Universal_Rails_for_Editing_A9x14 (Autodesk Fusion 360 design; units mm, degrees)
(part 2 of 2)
sketch "Sketch53" plane through (0, 97.7, 0) normal (0, -1, 0) x axis (1, 0, 0)
  line L1 (241.5, 1.5) -> (241.5, 15)
  line L2 (253.5, 1.5) -> (241.5, 1.5)
  line L3 (253.5, 15) -> (253.5, 1.5)
  line L4 (241.5, 15) -> (253.5, 15)
  circle C1 centre (245.5, 9) radius 1
  circle C2 centre (247.5, 9) radius 1
  dimension "d563" diameter C2 = 2
extrude "Extrude160" cut sketch "Sketch53" profile of C2 against normal blind 4
delete_face "DeleteFace57"
sketch "Sketch54" plane through (0, 97.7, 0) normal (0, -1, 0) x axis (1, 0, 0)
  line L1 (144.5, 13.2322) -> (144.5, 1)
  line L2 (132.5, 13.2322) -> (144.5, 13.2322)
  line L3 (132.5, 1) -> (132.5, 13.2322)
  line L4 (144.5, 1) -> (132.5, 1)
  circle C1 centre (138.5, 9) radius 1
  circle C2 centre (139.5, 9) radius 1
  point P2 (138.5, 9)
  coincident P2 C2
  dimension "d566" diameter C2 = 2
extrude "Extrude161" new body sketch "Sketch54" profile of C1 C2 along normal blind 1.9
delete_face "DeleteFace58"
extrude "Extrude162" cut of existing geometry blind -14
extrude "Extrude163" cut of existing geometry blind -1
extrude "Extrude164" add of existing geometry blind 1
fillet "Fillet54" radius 3
fillet "Fillet55" radius 3
chamfer "Chamfer16" distance 0.75
chamfer "Chamfer17" distance 0.75
chamfer "Chamfer18" distance 0.75
delete_face "DeleteFace59"
delete_face "DeleteFace60"
sketch "Sketch55" plane through (0, 99.2, 0) normal (0, 1, 0) x axis (-1, 0, 0)
  line L1 (-279, 4) -> (-279, 12.5)
  line L2 (-5, -1) -> (-274, -1)
  line L3 (0, 12.5) -> (0, 4)
  line L4 (-25, 15) -> (-2.5, 15)
  line L5 (-26.7678, 13.2322) -> (-25, 15)
  line L6 (-226.7678, 13.2322) -> (-26.7678, 13.2322)
  line L7 (-228.5355, 15) -> (-226.7678, 13.2322)
  line L8 (-276.5, 15) -> (-228.5355, 15)
  circle C1 centre (-139.5, 9) radius 1
  circle C2 centre (-12, 9) radius 1.75
  arc A1 centre (-276.5, 12.5) radius 2.5 clockwise from (-279, 12.5) to (-276.5, 15)
  arc A2 centre (-274, 4) radius 5 clockwise from (-274, -1) to (-279, 4)
  arc A3 centre (-5, 4) radius 5 clockwise from (0, 4) to (-5, -1)
  arc A4 centre (-2.5, 12.5) radius 2.5 clockwise from (-2.5, 15) to (0, 12.5)
  circle C3 centre (-140.5, 9) radius 1
  circle C4 centre (-248, 9) radius 1
  point P20 (-140.5, 9)
  coincident C1 P20
  dimension "d582" diameter C3 = 2
  dimension "d583" diameter C4 = 2
extrude "Extrude165" new body sketch "Sketch55" profile of C4 against normal blind 1.5
extrude "Extrude166" new body sketch "Sketch55" profile of C4 along normal blind 5.2
extrude "Extrude167" cut of existing geometry blind -29.5
extrude "Extrude168" add sketch "Sketch55" profile of C1 C3 along normal blind 2
extrude "Extrude169" new body sketch "Sketch55" profile of C1 C3 against normal blind 1.5
extrude "Extrude170" cut of existing geometry blind -19
delete_face "DeleteFace61"
extrude "Extrude171" cut of existing geometry blind -1
fillet "Fillet56" radius 3
combine "Combine10"
delete_face "DeleteFace62"
extrude "Extrude172" cut of existing geometry blind -0.5
fillet "Fillet57" radius 3
extrude "Extrude173" cut of existing geometry blind -2.1
extrude "Extrude174" add of existing geometry blind 2.4
delete_face "DeleteFace63"
extrude "Extrude175" add of existing geometry blind 2.4
delete_face "DeleteFace64"
extrude "Extrude176" add of existing geometry blind 2.4
delete_face "DeleteFace65"
delete_face "DeleteFace66"
delete_face "DeleteFace67"
delete_face "DeleteFace68"
delete_face "DeleteFace69"
delete_face "DeleteFace70"
delete_face "DeleteFace71"
delete_face "DeleteFace72"
delete_face "DeleteFace73"
delete_face "DeleteFace74"
delete_face "DeleteFace75"
delete_face "DeleteFace76"
delete_face "DeleteFace77"
delete_face "DeleteFace78"
delete_face "DeleteFace79"
delete_face "DeleteFace80"
delete_face "DeleteFace81"
delete_face "DeleteFace82"
extrude "Extrude177" add of existing geometry blind 6.35
delete_face "DeleteFace83"
delete_face "DeleteFace84"
delete_face "DeleteFace85"
delete_face "DeleteFace86"
delete_face "DeleteFace87"
delete_face "DeleteFace88"
delete_face "DeleteFace89"
delete_face "DeleteFace90"
delete_face "DeleteFace91"
delete_face "DeleteFace92"
delete_face "DeleteFace93"
delete_face "DeleteFace94"
delete_face "DeleteFace95"
delete_face "DeleteFace96"
delete_face "DeleteFace97"
delete_face "DeleteFace98"
delete_face "DeleteFace99"
delete_face "DeleteFace100"
delete_face "DeleteFace101"
delete_face "DeleteFace102"
delete_face "DeleteFace103"
extrude "Extrude178" add of existing geometry blind 5.55
delete_face "DeleteFace104"
delete_face "DeleteFace105"
delete_face "DeleteFace106"
delete_face "DeleteFace107"
sketch "Sketch56" plane through (0, 3.05, 0) normal (0, 1, 0) x axis (-1, 0, 0)
  line L1 (-26.4528, 4.7) -> (-18, 4.7)
  line L2 (-26.4523, 6.2374) -> (-26.4528, 4.7)
  line L3 (-26.4524, 6.5) -> (-26.4523, 6.2374)
  line L4 (-18, 6.5) -> (-26.4524, 6.5)
  line L5 (-18, 4.7) -> (-18, 6.5)
  line L6 (-18, 10.3) -> (-26.4528, 10.3)
  line L7 (-18, 8.5) -> (-18, 10.3)
  line L8 (-26.4524, 8.5) -> (-18, 8.5)
  line L9 (-26.4523, 8.7626) -> (-26.4524, 8.5)
  line L10 (-26.4528, 10.3) -> (-26.4523, 8.7626)
  line L11 (-0.5307, 10.3) -> (-6, 10.3)
  line L12 (-0.5307, 8.5) -> (-0.5307, 10.3)
  line L13 (-6, 8.5) -> (-0.5307, 8.5)
  line L14 (-6, 10.3) -> (-6, 8.5)
  line L15 (-118.9528, 4.7) -> (-93.0307, 4.7)
  line L16 (-118.9523, 6.2374) -> (-118.9528, 4.7)
  line L17 (-118.9524, 6.5) -> (-118.9523, 6.2374)
  line L18 (-93.0307, 6.5) -> (-118.9524, 6.5)
  line L19 (-93.0307, 4.7) -> (-93.0307, 6.5)
  line L20 (-158.6084, 10) -> (-157.0472, 10)
  line L21 (-158.6088, 8.7626) -> (-158.6084, 10)
  line L22 (-158.6088, 8.5) -> (-158.6088, 8.7626)
  line L23 (-185.5304, 8.5) -> (-158.6088, 8.5)
  line L24 (-185.5304, 10) -> (-185.5304, 8.5)
  line L25 (-185.5307, 10) -> (-185.5304, 10)
  line L26 (-185.5307, 8.5) -> (-185.5307, 10)
  line L27 (-194.75, 8.5) -> (-185.5307, 8.5)
  line L28 (-194.75, 10.3) -> (-194.75, 8.5)
  line L29 (-185.5307, 10.3) -> (-194.75, 10.3)
  line L30 (-185.5304, 10.3) -> (-185.5307, 10.3)
  line L31 (-158.6083, 10.3) -> (-185.5304, 10.3)
  line L32 (-158.4649, 10.3) -> (-158.6083, 10.3)
  line L33 (-206.75, 8.5) -> (-206.75, 10.3)
  line L34 (-211.4524, 8.5) -> (-206.75, 8.5)
  line L35 (-211.4523, 8.7626) -> (-211.4524, 8.5)
  line L36 (-211.4528, 10.3) -> (-211.4523, 8.7626)
  line L37 (-206.75, 10.3) -> (-211.4528, 10.3)
  line L38 (-66.1088, 8.7626) -> (-66.1083, 10.3)
  line L39 (-66.1088, 8.5) -> (-66.1088, 8.7626)
  line L40 (-93.0304, 8.5) -> (-66.1088, 8.5)
  line L41 (-93.0304, 10) -> (-93.0304, 8.5)
  line L42 (-93.0307, 10) -> (-93.0304, 10)
  line L43 (-93.0307, 8.5) -> (-93.0307, 10)
  line L44 (-118.9524, 8.5) -> (-93.0307, 8.5)
  line L45 (-118.9523, 8.7626) -> (-118.9524, 8.5)
  line L46 (-118.9528, 10.3) -> (-118.9523, 8.7626)
  line L47 (-93.0307, 10.3) -> (-118.9528, 10.3)
  line L48 (-93.0304, 10.3) -> (-93.0307, 10.3)
  line L49 (-66.1083, 10.3) -> (-93.0304, 10.3)
  line L50 (-158.6088, 6.5) -> (-185.5304, 6.5)
  line L51 (-158.6088, 6.2374) -> (-158.6088, 6.5)
  line L52 (-158.6083, 4.7) -> (-158.6088, 6.2374)
  line L53 (-185.5304, 4.7) -> (-158.6083, 4.7)
  line L54 (-185.5304, 6.4944) -> (-185.5304, 4.7)
  line L55 (-185.5304, 6.5) -> (-185.5304, 6.4944)
  line L56 (-194.75, 6.5) -> (-194.75, 4.7)
  line L57 (-185.5307, 6.5) -> (-194.75, 6.5)
  line L58 (-185.5307, 4.7) -> (-185.5307, 6.5)
  line L59 (-194.75, 4.7) -> (-185.5307, 4.7)
  line L60 (-0.5307, 6.5) -> (-6, 6.5)
  line L61 (-0.5307, 4.7) -> (-0.5307, 6.5)
  line L62 (-6, 4.7) -> (-0.5307, 4.7)
  line L63 (-6, 6.5) -> (-6, 4.7)
  line L64 (-251.1083, 4.7) -> (-251.1088, 6.2374)
  line L65 (-278.0304, 4.7) -> (-251.1083, 4.7)
  line L66 (-278.0304, 6.4944) -> (-278.0304, 4.7)
  line L67 (-278.0304, 6.5) -> (-278.0304, 6.4944)
  line L68 (-251.1088, 6.5) -> (-278.0304, 6.5)
  line L69 (-251.1088, 6.2374) -> (-251.1088, 6.5)
  line L70 (-206.75, 6.5) -> (-211.4524, 6.5)
  line L71 (-206.75, 4.7) -> (-206.75, 6.5)
  line L72 (-211.4528, 4.7) -> (-206.75, 4.7)
  line L73 (-211.4523, 6.2374) -> (-211.4528, 4.7)
  line L74 (-211.4524, 6.5) -> (-211.4523, 6.2374)
  line L75 (-251.1088, 8.7626) -> (-251.1083, 10.3)
  line L76 (-251.1088, 8.5) -> (-251.1088, 8.7626)
  line L77 (-278.0304, 8.5) -> (-251.1088, 8.5)
  line L78 (-278.0304, 10.3) -> (-278.0304, 8.5)
  line L79 (-251.1083, 10.3) -> (-278.0304, 10.3)
  line L80 (-66.1088, 6.5) -> (-93.0304, 6.5)
  line L81 (-66.1088, 6.2374) -> (-66.1088, 6.5)
  line L82 (-66.1083, 4.7) -> (-66.1088, 6.2374)
  line L83 (-93.0304, 4.7) -> (-66.1083, 4.7)
  line L84 (-93.0304, 6.4944) -> (-93.0304, 4.7)
  line L85 (-93.0304, 6.5) -> (-93.0304, 6.4944)
  line L86 (-185.05, 15) -> (-2, 15)
  line L87 (-185.9, 13.3526) -> (-185.9, 14.15)
  line L88 (-185.8932, 13.3525) -> (-185.9, 13.3526)
  line L89 (-185.8945, 13.2025) -> (-185.8932, 13.3525)
  line L90 (-202.0076, 12.4914) -> (-186.7518, 12.3599)
  line L91 (-279, 10.5) -> (-206.3608, 10.5)
  line L92 (-279, 10.3) -> (-279, 10.5)
  line L93 (-278.0307, 10.3) -> (-279, 10.3)
  line L94 (-278.0307, 8.5) -> (-278.0307, 10.3)
  line L95 (-279, 8.5) -> (-278.0307, 8.5)
  line L96 (-279, 6.5) -> (-279, 8.5)
  line L97 (-278.0307, 6.5) -> (-279, 6.5)
  line L98 (-278.0307, 4.7) -> (-278.0307, 6.5)
  line L99 (-279, 4.7) -> (-278.0307, 4.7)
  line L100 (-279, 4) -> (-279, 4.7)
  line L101 (-5, -1) -> (-274, -1)
  line L102 (0, 4.7) -> (0, 4)
  line L103 (-0.5304, 4.7) -> (0, 4.7)
  line L104 (-0.5304, 6.4944) -> (-0.5304, 4.7)
  line L105 (-0.5304, 6.5) -> (-0.5304, 6.4944)
  line L106 (0, 6.5) -> (-0.5304, 6.5)
  line L107 (0, 8.5) -> (0, 6.5)
  line L108 (-0.5304, 8.5) -> (0, 8.5)
  line L109 (-0.5304, 10.3) -> (-0.5304, 8.5)
  line L110 (0, 10.3) -> (-0.5304, 10.3)
  line L111 (0, 13) -> (0, 10.3)
  line L112 (-158.6089, 9.5) -> (-157, 9.5)
  line L113 (-158.6089, 10.8464) -> (-158.6089, 9.5)
  line L114 (-157, 10.8464) -> (-158.6089, 10.8464)
  line L115 (-157, 9.5) -> (-157, 10.8464)
  arc A1 centre (-158.4649, 6.8) radius 3.5 clockwise from (-158.4649, 10.3) to (-157.0472, 10)
  arc A2 centre (-185.05, 14.15) radius 0.85 clockwise from (-185.9, 14.15) to (-185.05, 15)
  arc A3 centre (-186.7445, 13.2099) radius 0.85 clockwise from (-185.8945, 13.2025) to (-186.7518, 12.3599)
  arc A4 centre (-202.0321, 9.6415) radius 2.85 clockwise from (-204.1965, 11.4958) to (-202.0076, 12.4914)
  arc A5 centre (-206.3608, 13.35) radius 2.85 clockwise from (-204.1965, 11.4958) to (-206.3608, 10.5)
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  horizontal L112
  vertical L113
  horizontal L114
  vertical L115
extrude "Extrude179" add sketch "Sketch56" profile of L20 L21 L31 L32 A1 L112 L113 L114 L115 against normal blind 0.6
extrude "Extrude180" cut of existing geometry blind -3.95
delete_face "DeleteFace108"
delete_face "DeleteFace109"
delete_face "DeleteFace110"
extrude "Extrude181" add of existing geometry blind 15.7
extrude "Extrude182" add of existing geometry blind 15.685
extrude "Extrude183" add of existing geometry blind 4.5
delete_face "DeleteFace111"
extrude "Extrude184" add of existing geometry blind 3.165
extrude "Extrude185" cut of existing geometry blind 3.151
extrude "Extrude186" add of existing geometry blind 3.151
base_mesh_feature "Base Mesh Feature4"
copy_paste_bodies "CopyPasteBodies12"
move "Move31"
move "Move32"
copy_paste_bodies "CopyPasteBodies13"
move "Move33"
move "Move34"
move "Move35"
combine "Combine11"
sketch "Sketch57" plane through (0, 99.2, 0) normal (0, 1, 0) x axis (-1, 0, 0)
  line L1 (-279, 4) -> (-279, 12.5)
  line L2 (-5, -1) -> (-274, -1)
  line L3 (0, 12.5) -> (0, 4)
  line L4 (-25, 15) -> (-2.5, 15)
  line L5 (-26.7678, 13.2322) -> (-25, 15)
  line L6 (-226.7678, 13.2322) -> (-26.7678, 13.2322)
  line L7 (-228.5355, 15) -> (-226.7678, 13.2322)
  line L8 (-276.5, 15) -> (-228.5355, 15)
  line L9 (0, -2.3809) -> (34.6517, -2.3809)
  line L10 (0, 12.5) -> (0, -2.3809)
  line L11 (34.6517, 12.5) -> (0, 12.5)
  line L12 (34.6517, -2.3809) -> (34.6517, 12.5)
  arc A1 centre (-276.5, 12.5) radius 2.5 clockwise from (-279, 12.5) to (-276.5, 15)
  arc A2 centre (-274, 4) radius 5 clockwise from (-274, -1) to (-279, 4)
  arc A3 centre (-5, 4) radius 5 clockwise from (0, 4) to (-5, -1)
  arc A4 centre (-2.5, 12.5) radius 2.5 clockwise from (-2.5, 15) to (0, 12.5)
  point P11 (0, 12.5)
  point P20 (0, 12.5)
  horizontal L9
  vertical L10
  horizontal L11
  vertical L12
  coincident P11 P20
extrude "Extrude187" cut sketch "Sketch57" profile of L3 L9 L10 L11 L12 against normal blind 27
sketch "Sketch58" plane through (0, 99.2, 0) normal (0, 1, 0) x axis (-1, 0, 0)
  line L1 (-279, 4) -> (-279, 12.5)
  line L2 (-5, -1) -> (-274, -1)
  line L3 (0, 12.5) -> (0, 4)
  line L4 (-25, 15) -> (-2.5, 15)
  line L5 (-26.7678, 13.2322) -> (-25, 15)
  line L6 (-226.7678, 13.2322) -> (-26.7678, 13.2322)
  line L7 (-228.5355, 15) -> (-226.7678, 13.2322)
  line L8 (-276.5, 15) -> (-228.5355, 15)
  line L9 (-279, 2.4683) -> (-310.8801, 2.4683)
  line L10 (-279, 11.4896) -> (-279, 2.4683)
  line L11 (-310.8801, 11.4896) -> (-279, 11.4896)
  line L12 (-310.8801, 2.4683) -> (-310.8801, 11.4896)
  arc A1 centre (-276.5, 12.5) radius 2.5 clockwise from (-279, 12.5) to (-276.5, 15)
  arc A2 centre (-274, 4) radius 5 clockwise from (-274, -1) to (-279, 4)
  arc A3 centre (-5, 4) radius 5 clockwise from (0, 4) to (-5, -1)
  arc A4 centre (-2.5, 12.5) radius 2.5 clockwise from (-2.5, 15) to (0, 12.5)
  point P20 (-279, 11.4896)
  horizontal L9
  vertical L10
  horizontal L11
  vertical L12
  coincident L1 P20
extrude "Extrude188" cut sketch "Sketch58" profile of L1 L9 L10 L11 L12 against normal blind 18
combine "Combine12"
extrude "Extrude189" cut of existing geometry blind 0
sketch "Sketch59" plane through (0, 0, 15) normal (0, 0, 1) x axis (-1, 0, 0)
  line L1 (-279, 0.85) -> (-2, 0.85)
  line L2 (-279, -3.05) -> (-279, 0.85)
  line L3 (-2, -3.05) -> (-279, -3.05)
  line L4 (-2, 0.85) -> (-2, -3.05)
  line L5 (-313.3512, -35) -> (15, -35)
  line L6 (-313.3512, 31.902) -> (-313.3512, -35)
  line L7 (15, 31.902) -> (-313.3512, 31.902)
  line L8 (15, -35) -> (15, 31.902)
  horizontal L5
  vertical L6
  horizontal L7
  vertical L8
extrude "Extrude190" cut sketch "Sketch59" against normal blind 60
sketch "Sketch60" plane through (279, 0, 0) normal (1, 0, 0) x axis (0, 1, 0)
  line L1 (95.3, 10.3) -> (95.3, 12.5)
  line L2 (94.9791, 10.3) -> (95.3, 10.3)
  line L3 (94.8927, 10.3) -> (94.9791, 10.3)
  line L4 (94.6514, 10.3) -> (94.8927, 10.3)
  line L5 (94.1537, 10.3) -> (94.6514, 10.3)
  line L6 (93.2572, 10.3) -> (94.1537, 10.3)
  line L7 (92.2048, 10.3) -> (93.2572, 10.3)
  line L8 (92.2048, 9.9244) -> (92.2048, 10.3)
  line L9 (92.2048, 8.5) -> (92.2048, 9.9244)
  line L10 (92.6073, 8.5) -> (92.2048, 8.5)
  line L11 (93.2572, 8.5) -> (92.6073, 8.5)
  line L12 (94.1537, 8.5) -> (93.2572, 8.5)
  line L13 (94.6514, 8.5) -> (94.1537, 8.5)
  line L14 (94.8927, 8.5) -> (94.6514, 8.5)
  line L15 (94.9791, 8.5) -> (94.8927, 8.5)
  line L16 (95.167, 8.5) -> (94.9791, 8.5)
  line L17 (95.167, 8.3539) -> (95.167, 8.5)
  line L18 (95.167, 6.5) -> (95.167, 8.3539)
  line L19 (94.9791, 6.5) -> (95.167, 6.5)
  line L20 (94.8927, 6.5) -> (94.9791, 6.5)
  line L21 (94.6514, 6.5) -> (94.8927, 6.5)
  line L22 (94.1537, 6.5) -> (94.6514, 6.5)
  line L23 (93.2572, 6.5) -> (94.1537, 6.5)
  line L24 (92.6073, 6.5) -> (93.2572, 6.5)
  line L25 (92.2048, 6.5) -> (92.6073, 6.5)
  line L26 (92.2048, 6.1244) -> (92.2048, 6.5)
  line L27 (92.2048, 4.7) -> (92.2048, 6.1244)
  line L28 (93.2572, 4.7) -> (92.2048, 4.7)
  line L29 (94.1537, 4.7) -> (93.2572, 4.7)
  line L30 (94.6515, 4.7) -> (94.1537, 4.7)
  line L31 (94.8928, 4.7) -> (94.6515, 4.7)
  line L32 (94.9791, 4.7) -> (94.8928, 4.7)
  line L33 (95.3, 4.7) -> (94.9791, 4.7)
  line L34 (95.3, 4) -> (95.3, 4.7)
  line L35 (99.2, 4) -> (95.3, 4)
  line L36 (99.2, 12.5) -> (99.2, 4)
  line L37 (95.3, 12.5) -> (99.2, 12.5)
  line L38 (113, 22) -> (81, 22)
  line L39 (113, -11) -> (113, 22)
  line L40 (81, -11) -> (113, -11)
  line L41 (81, 22) -> (81, -11)
  horizontal L38
  vertical L39
  horizontal L40
  vertical L41
extrude "Extrude191" cut sketch "Sketch60" against normal blind 1
remove_body "RemoveBody1"
step "MeshRemove"
remove_body "RemoveBody2"
sketch "Sketch61" plane through (0, 0, -1) normal (0, 0, -1) x axis (1, 0, 0)
  line L1 (6, -95.3) -> (274, -95.3)
  line L2 (6, -95.25) -> (6, -95.3)
  line L3 (5, -95.25) -> (6, -95.25)
  line L4 (5, -99.2) -> (5, -95.25)
  line L5 (274, -99.2) -> (5, -99.2)
  line L6 (274, -95.3) -> (274, -99.2)
  line L7 (252, -98) -> (260, -98)
  line L8 (252, -98) -> (252, -98)
  line L9 (260, -98) -> (252, -98)
  line L10 (31.5, -77.4611) -> (-7.2326, -77.4611)
  line L11 (31.5, -96.5) -> (31.5, -77.4611)
  line L12 (-7.2326, -96.5) -> (31.5, -96.5)
  line L13 (-7.2326, -77.4611) -> (-7.2326, -96.5)
  horizontal L10
  vertical L11
  horizontal L12
  vertical L13
extrude "Extrude192" cut sketch "Sketch61" profile of L1 L2 L3 L4 L10 L11 L12 L13 against normal blind 43.5
sketch "Sketch62" plane through (0, 0, -1) normal (0, 0, -1) x axis (1, 0, 0)
  line L1 (252, -98) -> (260, -98)
  line L2 (252, -98) -> (252, -98)
  line L3 (260, -98) -> (252, -98)
  line L4 (31.5, -96.5) -> (31.5, -95.3)
  line L5 (5, -96.5) -> (31.5, -96.5)
  line L6 (5, -99.2) -> (5, -96.5)
  line L7 (274, -99.2) -> (5, -99.2)
  line L8 (274, -95.3) -> (274, -99.2)
  line L9 (31.5, -95.3) -> (274, -95.3)
  line L10 (281, -79) -> (228, -79)
  line L11 (281, -97) -> (281, -79)
  line L12 (228, -97) -> (281, -97)
  line L13 (228, -79) -> (228, -97)
  horizontal L10
  vertical L11
  horizontal L12
  vertical L13
extrude "Extrude193" cut sketch "Sketch62" profile of L8 L9 L10 L11 L12 L13 against normal blind 45
extrude "Extrude194" add of existing geometry blind 1.7
extrude "Extrude195" add of existing geometry blind 1.2
extrude "Extrude196" cut of existing geometry blind 0
extrude "Extrude197" add of existing geometry blind 2.5
extrude "Extrude198" cut of existing geometry blind -2.5
extrude "Extrude199" add of existing geometry blind 4.5
extrude "Extrude200" cut of existing geometry blind -4.5
fillet "Fillet58" radius 2.75
sketch "Sketch63" plane through (0, 95.3, 0) normal (0, -1, 0) x axis (1, 0, 0)
  line L1 (123.5806, 10.2987) -> (123.5806, 10.3)
  line L2 (123.5806, 4.7) -> (123.5806, 10.2987)
  line L3 (119.8886, 4.7) -> (123.5806, 4.7)
  line L4 (119.7054, 4.7) -> (119.8886, 4.7)
  line L5 (119.5251, 4.7) -> (119.7054, 4.7)
  line L6 (118.8848, 4.7) -> (119.5251, 4.7)
  line L7 (96.2745, 4.7) -> (118.8848, 4.7)
  line L8 (92.1308, 4.7) -> (96.2745, 4.7)
  line L9 (92.1308, 6.3538) -> (92.1308, 4.7)
  line L10 (92.1308, 6.8087) -> (92.1308, 6.3538)
  line L11 (92.1308, 8.6463) -> (92.1308, 6.8087)
  line L12 (92.1308, 10.3) -> (92.1308, 8.6463)
  line L13 (96.2745, 10.3) -> (92.1308, 10.3)
  line L14 (116.9221, 10.3) -> (96.2745, 10.3)
  line L15 (119.4448, 10.3) -> (116.9221, 10.3)
  line L16 (119.4808, 10.3) -> (119.4448, 10.3)
  line L17 (119.5671, 10.3) -> (119.4808, 10.3)
  line L18 (119.7041, 10.3) -> (119.5671, 10.3)
  line L19 (119.8886, 10.3) -> (119.7041, 10.3)
  line L20 (123.5806, 10.3) -> (119.8886, 10.3)
  line L21 (88.7076, 10.3) -> (66.3547, 10.3)
  line L22 (92.1304, 10.3) -> (88.7076, 10.3)
  line L23 (92.1304, 8.6463) -> (92.1304, 10.3)
  line L24 (92.1304, 8.1912) -> (92.1304, 8.6463)
  line L25 (92.1304, 6.3537) -> (92.1304, 8.1912)
  line L26 (92.1304, 4.7) -> (92.1304, 6.3537)
  line L27 (92.0906, 4.7) -> (92.1304, 4.7)
  line L28 (92.0666, 4.7) -> (92.0906, 4.7)
  line L29 (92.043, 4.7) -> (92.0666, 4.7)
  line L30 (92.0203, 4.7) -> (92.043, 4.7)
  line L31 (91.9991, 4.7) -> (92.0203, 4.7)
  line L32 (91.9799, 4.7) -> (91.9991, 4.7)
  line L33 (91.8202, 4.7) -> (91.9799, 4.7)
  line L34 (91.5506, 4.7) -> (91.8202, 4.7)
  line L35 (91.0858, 4.7) -> (91.5506, 4.7)
  line L36 (90.3931, 4.7) -> (91.0858, 4.7)
  line L37 (89.5311, 4.7) -> (90.3931, 4.7)
  line L38 (88.7076, 4.7) -> (89.5311, 4.7)
  line L39 (66.3547, 4.7) -> (88.7076, 4.7)
  line L40 (65.7303, 4.7) -> (66.3547, 4.7)
  line L41 (65.557, 4.7) -> (65.7303, 4.7)
  line L42 (65.3725, 4.7) -> (65.557, 4.7)
  line L43 (61.6806, 4.7) -> (65.3725, 4.7)
  line L44 (61.6806, 10.2988) -> (61.6806, 4.7)
  line L45 (61.6806, 10.3) -> (61.6806, 10.2988)
  line L46 (65.3725, 10.3) -> (61.6806, 10.3)
  line L47 (65.557, 10.3) -> (65.3725, 10.3)
  line L48 (65.7303, 10.3) -> (65.557, 10.3)
  line L49 (66.3547, 10.3) -> (65.7303, 10.3)
  line L50 (158.4538, 5.4776) -> (158.4538, 4.7)
  line L51 (158.4538, 7.5) -> (158.4538, 5.4776)
  line L52 (158.4538, 8.2776) -> (158.4538, 7.5)
  line L53 (158.4538, 10.3) -> (158.4538, 8.2776)
  line L54 (158.9657, 10.3) -> (158.4538, 10.3)
  line L55 (159.0651, 10.3) -> (158.9657, 10.3)
  line L56 (160.4346, 10.3) -> (159.0651, 10.3)
  line L57 (180.9195, 10.3) -> (160.4346, 10.3)
  line L58 (184.5474, 10.3) -> (180.9195, 10.3)
  line L59 (184.5474, 8.5472) -> (184.5474, 10.3)
  line L60 (184.5474, 8.4004) -> (184.5474, 8.5472)
  line L61 (184.5474, 6.4528) -> (184.5474, 8.4004)
  line L62 (184.5474, 4.7) -> (184.5474, 6.4528)
  line L63 (184.5052, 4.7) -> (184.5474, 4.7)
  line L64 (184.4797, 4.7) -> (184.5052, 4.7)
  line L65 (184.4547, 4.7) -> (184.4797, 4.7)
  line L66 (184.4307, 4.7) -> (184.4547, 4.7)
  line L67 (184.4082, 4.7) -> (184.4307, 4.7)
  line L68 (184.3879, 4.7) -> (184.4082, 4.7)
  line L69 (184.2186, 4.7) -> (184.3879, 4.7)
  line L70 (183.9329, 4.7) -> (184.2186, 4.7)
  line L71 (183.4402, 4.7) -> (183.9329, 4.7)
  line L72 (182.706, 4.7) -> (183.4402, 4.7)
  line L73 (181.7924, 4.7) -> (182.706, 4.7)
  line L74 (180.9195, 4.7) -> (181.7924, 4.7)
  line L75 (160.4346, 4.7) -> (180.9195, 4.7)
  line L76 (159.0651, 4.7) -> (160.4346, 4.7)
  line L77 (158.9657, 4.7) -> (159.0651, 4.7)
  line L78 (158.4538, 4.7) -> (158.9657, 4.7)
  line L79 (211.6413, 4.7) -> (211.6413, 6.7224)
  line L80 (211.1294, 4.7) -> (211.6413, 4.7)
  line L81 (211.03, 4.7) -> (211.1294, 4.7)
  line L82 (209.6605, 4.7) -> (211.03, 4.7)
  line L83 (188.9398, 4.7) -> (209.6605, 4.7)
  line L84 (184.5477, 4.7) -> (188.9398, 4.7)
  line L85 (184.5477, 6.4529) -> (184.5477, 4.7)
  line L86 (184.5477, 6.5995) -> (184.5477, 6.4529)
  line L87 (184.5477, 8.5472) -> (184.5477, 6.5995)
  line L88 (184.5477, 10.3) -> (184.5477, 8.5472)
  line L89 (188.9398, 10.3) -> (184.5477, 10.3)
  line L90 (210.8246, 10.3) -> (188.9398, 10.3)
  line L91 (211.614, 10.3) -> (210.8246, 10.3)
  line L92 (211.6413, 10.3) -> (211.614, 10.3)
  line L93 (211.6413, 9.5224) -> (211.6413, 10.3)
  line L94 (211.6413, 7.5) -> (211.6413, 9.5224)
  line L95 (211.6413, 6.7224) -> (211.6413, 7.5)
  line L96 (278, 4.7) -> (278, 2.1292)
  line L97 (276.9978, 4.7) -> (278, 4.7)
  line L98 (276.9978, 6.4078) -> (276.9978, 4.7)
  line L99 (276.9978, 6.6945) -> (276.9978, 6.4078)
  line L100 (276.9978, 8.5922) -> (276.9978, 6.6945)
  line L101 (276.9978, 10.3) -> (276.9978, 8.5922)
  line L102 (278, 10.3) -> (276.9978, 10.3)
  line L103 (278, 14.5) -> (278, 10.3)
  line L104 (228.5355, 15) -> (276.5, 15)
  line L105 (226.7678, 13.2322) -> (228.5355, 15)
  line L106 (26.7678, 13.2322) -> (226.7678, 13.2322)
  line L107 (25, 15) -> (26.7678, 13.2322)
  line L108 (2.5, 15) -> (25, 15)
  line L109 (0, 10.3) -> (0, 12.5)
  line L110 (3.8898, 10.3) -> (0, 10.3)
  line L111 (25.7745, 10.3) -> (3.8898, 10.3)
  line L112 (26.564, 10.3) -> (25.7745, 10.3)
  line L113 (26.5913, 10.3) -> (26.564, 10.3)
  line L114 (26.5913, 9.5225) -> (26.5913, 10.3)
  line L115 (26.5913, 7.5) -> (26.5913, 9.5225)
  line L116 (26.5913, 6.7225) -> (26.5913, 7.5)
  line L117 (26.5913, 4.7) -> (26.5913, 6.7225)
  line L118 (26.0794, 4.7) -> (26.5913, 4.7)
  line L119 (25.98, 4.7) -> (26.0794, 4.7)
  line L120 (24.6105, 4.7) -> (25.98, 4.7)
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extrude "Extrude201" cut sketch "Sketch63" along normal blind 3
sketch "Sketch64" plane through (0, 95.1375, 0) normal (0, -1, 0) x axis (1, 0, 0)
  line L1 (92.1304, 6.5) -> (66.1825, 6.5)
  line L2 (66.1825, 8.5) -> (92.1304, 6.5)
  line L3 (66.1825, 6.5) -> (66.1825, 8.5)
  line L4 (127.9194, 8.5) -> (66.1825, 8.5)
  line L5 (127.9194, 6.5) -> (127.9194, 8.5)
  line L6 (66.1825, 6.5) -> (127.9194, 6.5)
  line L7 (66.1825, 8.5) -> (66.1825, 6.5)
  line L8 (61.8061, 8.5) -> (127.9194, 8.5)
  line L9 (61.8061, 6.5) -> (61.8061, 8.5)
  line L10 (127.9194, 6.5) -> (61.8061, 6.5)
  line L11 (127.9194, 8.5) -> (127.9194, 6.5)
  point P4 (66.1825, 8.5)
  point P5 (66.1825, 8.5)
  horizontal L4
  vertical L5
  horizontal L6
  vertical L7
  coincident P4 P5
  horizontal L8
  vertical L9
  horizontal L10
  vertical L11
copy_paste_bodies "CopyPasteBodies14"
move "Move39"
mirror "Mirror1" mirrorStitchTolerance 0.1 bodies "Side 2"
remove_body "RemoveBody3"
move "Move40"
extrude "Extrude59" cut of existing geometry blind -2
extrude "Extrude60" add of existing geometry blind 2
extrude "Extrude61" cut of existing geometry blind -35
extrude "Extrude62" cut of existing geometry blind -20
extrude "Extrude63" cut of existing geometry blind -25
extrude "Extrude64" cut of existing geometry blind -45
extrude "Extrude65" cut of existing geometry blind -30
extrude "Extrude66" cut of existing geometry blind -45
extrude "Extrude67" cut of existing geometry blind -35
extrude "Extrude68" cut of existing geometry blind -35
extrude "Extrude69" cut of existing geometry blind 1
extrude "Extrude70" add of existing geometry blind 1
fillet "Fillet1" radius 5
extrude "Extrude71" add of existing geometry blind 25.5
extrude "Extrude72" add of existing geometry blind 1.9
fillet "Fillet2" radius 5
fillet "Fillet3" radius 5
fillet "Fillet4" radius 5
fillet "Fillet5" radius 3
fillet "Fillet6" radius 3
fillet "Fillet7" radius 5
fillet "Fillet8" radius 3
fillet "Fillet9" radius 3
fillet "Fillet10" radius 3
sketch "Sketch33" plane through (0, 0, 0) normal (0, 0, 1) x axis (-1, 0, 0)
  line L1 (-23, 1) -> (-23, 0)
  line L2 (-153, 1) -> (-23, 1)
  line L3 (-153, -7.9003) -> (-153, 1)
  line L4 (-126.1773, -99) -> (-126.1773, -90.6435)
  line L5 (-23, -99) -> (-126.1773, -99)
  line L6 (-23, -98) -> (-23, -99)
  line L7 (-3, -98) -> (-23, -98)
  line L8 (-3, -99) -> (-3, -98)
  line L9 (0, -96) -> (-3, -99)
  line L10 (0, -2) -> (0, -96)
  line L11 (-3, 1) -> (0, -2)
  line L12 (-3, 0) -> (-3, 1)
  line L13 (-23, 0) -> (-3, 0)
  line L14 (-310, -49) -> (-2.75, -49)
  line L15 (13, -49) -> (-2.75, -49)
  line L16 (-310, -19) -> (-2.75, -19)
  line L17 (13, -19) -> (-2.75, -19)
  line L18 (-310, -79) -> (-2.75, -79)
  line L19 (13, -79) -> (-2.75, -79)
  arc A1 centre (-138.75, -49) radius 43.5 clockwise from (-153, -7.9003) to (-126.1773, -90.6435)
  circle C1 centre (-5.0257, -7.7757) radius 2
  circle C2 centre (-97.5257, -7.7757) radius 2
  circle C3 centre (-4.9009, -90.0991) radius 2
  circle C4 centre (-87.4743, -90.2243) radius 2
  circle C5 centre (-97.5257, -90.2243) radius 2
  circle C6 centre (-87.4743, -7.7757) radius 2
  circle C7 centre (-46.25, -49) radius 43.5
  point P24 (-2.75, -49)
  coincident C7 P24
  perpendicular L10 L14
  parallel L14 L15
  dimension "d272" = 30
  dimension "d273" = -30
extrude "Extrude73" cut sketch "Sketch33" profile of A1 L10 C7 L14 L15 L17 L16 L19 L18 against normal blind 30 bodies "Part 1 (1)"
sketch "Sketch34" plane through (0, 0, 0) normal (0, 0, 1) x axis (-1, 0, 0)
  line L1 (-127.5, -99) -> (-127.5, -98)
  line L2 (-126.1773, -99) -> (-127.5, -99)
  line L3 (-126.1773, -90.6435) -> (-126.1773, -99)
  line L4 (-153, 1) -> (-153, -7.9003)
  line L5 (-187.75, 1) -> (-153, 1)
  line L6 (-187.75, 0) -> (-187.75, 1)
  line L7 (-209.75, 0) -> (-187.75, 0)
  line L8 (-209.75, 1) -> (-209.75, 0)
  line L9 (-276.5, 1) -> (-209.75, 1)
  line L10 (-279, -1.5) -> (-276.5, 1)
  line L11 (-279, -96.5) -> (-279, -1.5)
  line L12 (-278.25, -97.25) -> (-279, -96.5)
  line L13 (-277.5, -98) -> (-278.25, -97.25)
  line L14 (-256.5, -99) -> (-276.5, -99)
  line L15 (-256.5, -98) -> (-256.5, -99)
  line L16 (-234.5, -98) -> (-256.5, -98)
  line L17 (-234.5, -99) -> (-234.5, -98)
  line L18 (-149.5, -99) -> (-234.5, -99)
  line L19 (-149.5, -98) -> (-149.5, -99)
  line L20 (-127.5, -98) -> (-149.5, -98)
  line L21 (-50, -49) -> (-279, -49)
  line L22 (-50, -19) -> (-279, -19)
  line L23 (-50, -79) -> (-279, -79)
  line L24 (-276.5, -99) -> (-277.5, -98)
  arc A1 centre (-138.75, -49) radius 43.5 clockwise from (-126.1773, -90.6435) to (-153, -7.9003)
  circle C1 centre (-272.4743, -7.7757) radius 2
  circle C2 centre (-272.4743, -90.2243) radius 2
  circle C3 centre (-231.25, -49) radius 43.5
  circle C4 centre (-179.9743, -7.7757) radius 2
  circle C5 centre (-190.0257, -90.2243) radius 2
  circle C6 centre (-190.0257, -7.7757) radius 2
  circle C7 centre (-179.9743, -90.2243) radius 2
  point P32 (-279, -49)
  midpoint L11 P32
  perpendicular L11 L21
  dimension "d276" = -30
  dimension "d277" = 30
fillet "Fillet13" radius 10
extrude "Extrude74" cut sketch "Sketch34" profile of A1 L11 C3 L21 L22 L23 against normal blind 45 bodies "Part 2 (1)"
fillet "Fillet11" radius 10
fillet "Fillet12" radius 10
fillet "Fillet14" radius 10
fillet "Fillet15" radius 10
fillet "Fillet16" radius 10
fillet "Fillet17" radius 10
copy_paste_bodies "CopyPasteBodies1"
move "Move1"
copy_paste_bodies "CopyPasteBodies2"
move "Move2"
extrude "Extrude37" cut sketch "Sketch27" profile of L2 L3 L4 C1 L9 L10 L12 L13 L15 against normal blind 45
extrude "Extrude75" add of existing geometry blind 0.5 bodies "Part 1 (1)"
fillet "Fillet18" radius 5
extrude "Extrude76" add of existing geometry blind 0.5 bodies "Part 2 (1)"
fillet "Fillet19" radius 5
fillet "Fillet20" radius 10
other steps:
base_feature "Base Feature3" bodies "Part 2"
base_feature "Base Feature4" bodies "Whole Thing"
base_feature "Base Feature5" bodies "(1)", "(1) (1)"
base_feature "Base Feature6" bodies "(1) (1)", "(1) (1) (1)"
base_feature "Base Feature7" bodies "(1) (1) (1)", "(1) (1) (1) (3)"
base_feature "Base Feature8" bodies "(1) (1) (1) (3)", "(1) (1) (1) (3) (1)"
base_feature "Base Feature9" bodies "(1) (1) (2)"
base_feature "Base Feature10" bodies "(1) (1) (1) (3) (1)", "Side 2"
base_feature "Base Feature11" bodies "(1) (1) (1) (3) (2)"
base_feature "Base Feature13"
base_feature "Base Feature14"
base_feature "Base Feature15" bodies "Side 1", "Side 1 (1)"
base_feature "Base Feature1" bodies "Part 1 (1)", "Part 1 (1) (1)"
base_feature "Base Feature2" bodies "Part 1 (1) (1)", "Part 1 (1) (1) (1)"
named bodies: "Part 1", "Part 2", "Whole Thing", "Part 1 (1)", "Part 2 (1)", "Part 1 (1) (1)", "Part 1 (1) (1) (1)", "(1)", "(1) (1)", "(1) (1) (1)", "(1) (1) (1) (1)", "(1) (1) (1) (2)", "(1) (1) (1) (3)", "(1) (1) (1) (3) (1)", "(1) (1) (2)", "Side 2", "(1) (1) (1) (3) (1) (1) (1)", "(1) (1) (1) (3) (2)", "(1) (1) (1) (3) (3)", "(1) (1) (1) (3) (4)", "(1) (1) (1) (3) (2) (1)", "Side 1", "(1) (1) (1) (3) (1) (1) (1) (1)", "(1) (1) (1) (3) (4) (1)", "(1) (1) (1) (3) (4) (2)", "(1) (1) (1) (3) (4) (3)", "(1) (1) (1) (3) (4) (4)", "(1) (1) (1) (3) (4) (5)", "Side 2 (1)", "Side 2 (2)", "Side 1 (1)"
